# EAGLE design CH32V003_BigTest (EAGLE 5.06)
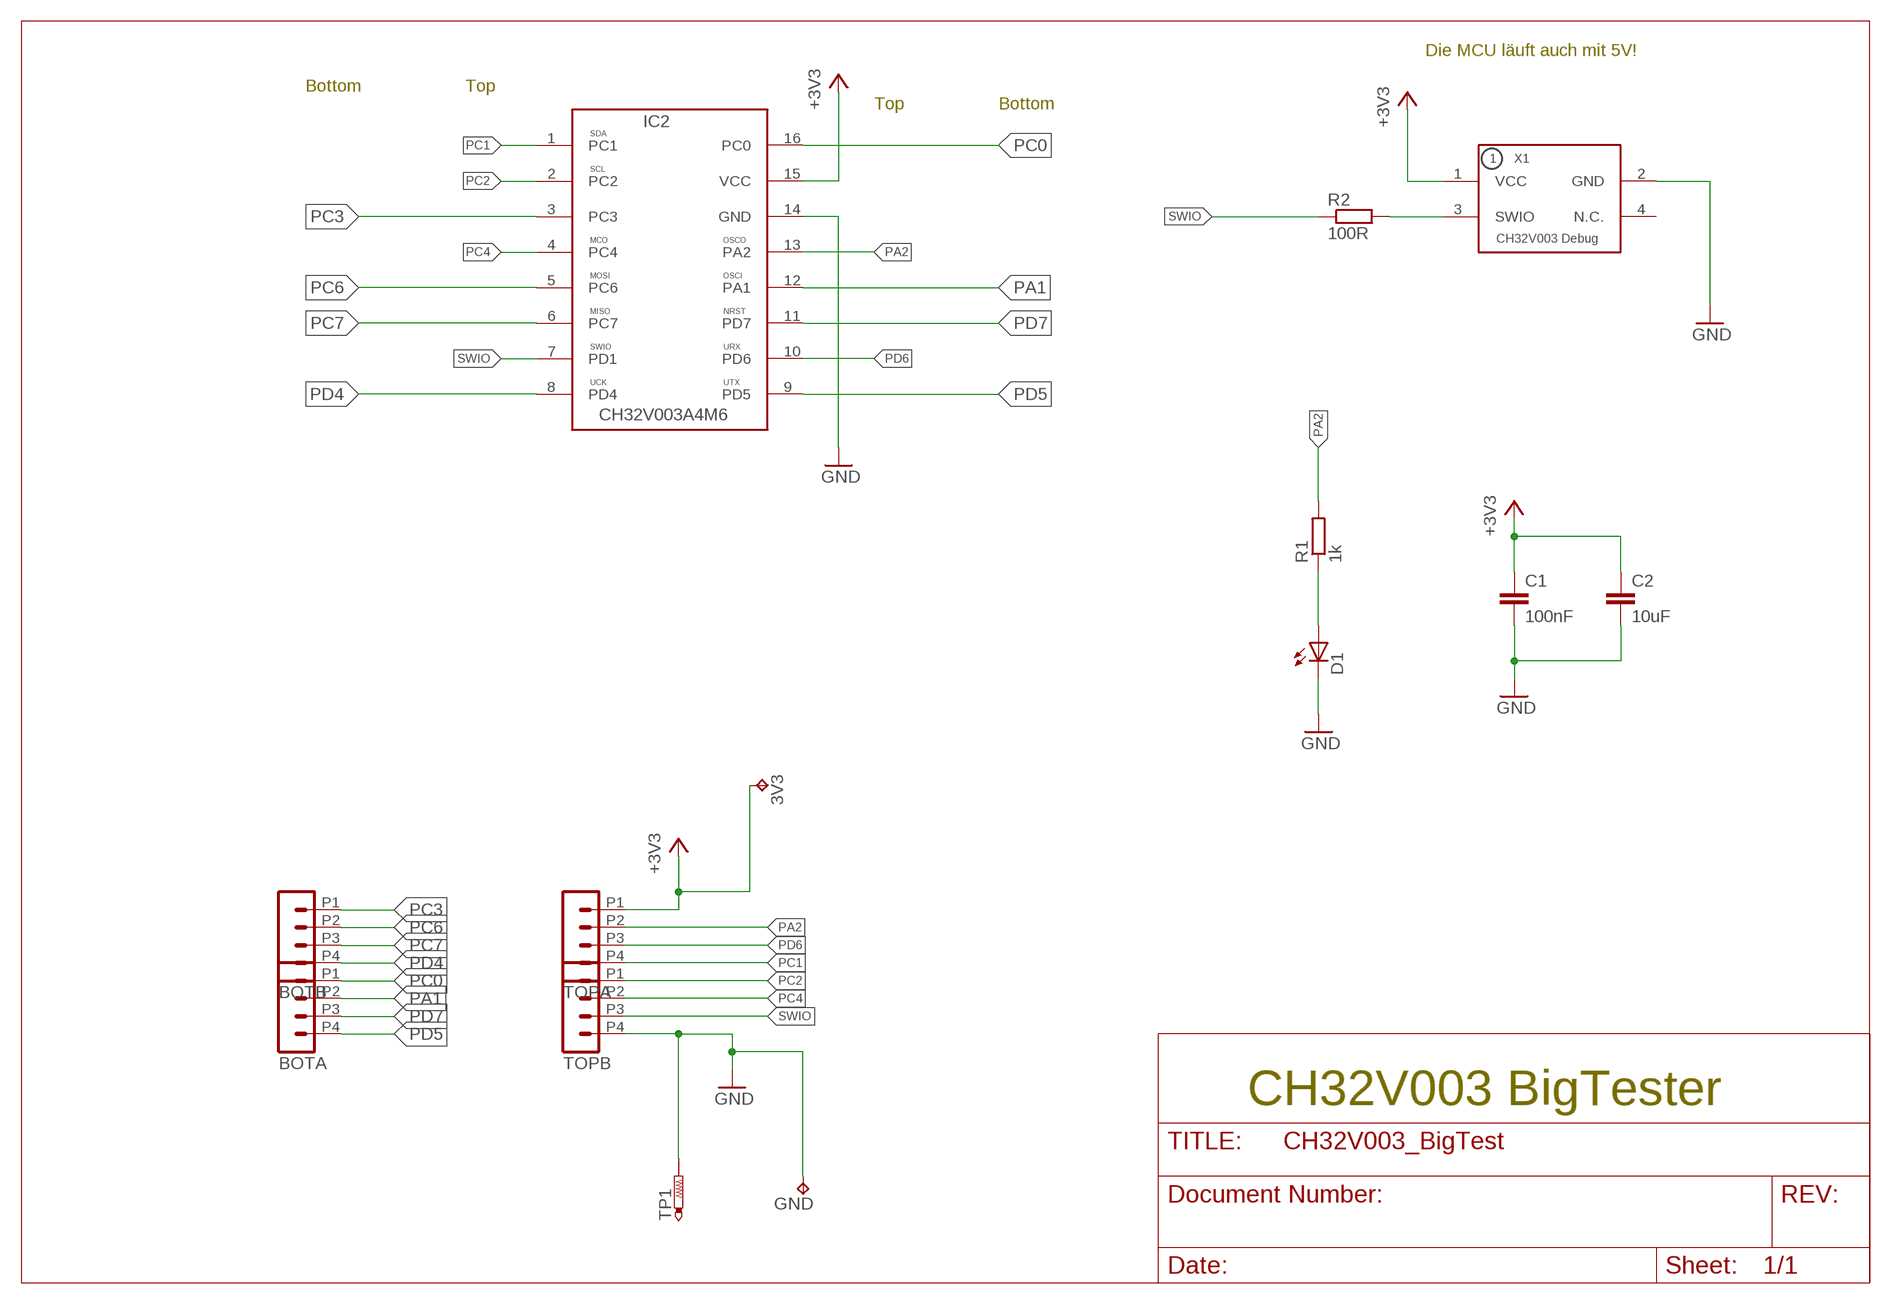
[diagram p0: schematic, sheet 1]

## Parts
3V3  TPB2,54  [B2,54]
BOTA  MA04-1SMD  [MA04-1SMD]
BOTB  MA04-1SMD  [MA04-1SMD]
C1  100nF  C-EUC0603  [C0603]
C2  10uF  C-EUC1210  [C1210]
D1  LEDCHIP-LED0603  [CHIP-LED0603]
GND  TPB2,54  [B2,54]
IC2  CH32V003A4M6  [SO16]
R1  1k  R-EU_R0603  [R0603]
R2  100R  R-EU_R0603  [R0603]
TOPA  MA04-1SMD  [MA04-1SMD]
TOPB  MA04-1SMD  [MA04-1SMD]
TP1  GND  TEST_OESE  [TEST_HAKEN]
X1  CH32V003_DEBUG  [CH32V003_DEBUG]

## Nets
+3V3: 3V3.PP(TP) C1.1 C2.1 IC2.15(VCC) TOPA.P1 X1.1(VCC)
GND: C1.2 C2.2 D1.C GND.PP(TP) IC2.14(GND) TOPB.P4 TP1.P$1(TP) X1.2(GND)
N$1: R2.2 X1.3(SWIO)
N$2: D1.A R1.1
PA1: BOTA.P2 IC2.12(PA1)
PA2: IC2.13(PA2) R1.2 TOPA.P2
PC0: BOTA.P1 IC2.16(PC0)
PC1: IC2.1(PC1) TOPA.P4
PC2: IC2.2(PC2) TOPB.P1
PC3: BOTB.P1 IC2.3(PC3)
PC4: IC2.4(PC4) TOPB.P2
PC6: BOTB.P2 IC2.5(PC6)
PC7: BOTB.P3 IC2.6(PC7)
PD4: BOTB.P4 IC2.8(PD4)
PD5: BOTA.P4 IC2.9(PD5)
PD6: IC2.10(PD6) TOPA.P3
PD7: BOTA.P3 IC2.11(PD7)
SWIO: IC2.7(PD1) R2.1 TOPB.P3
Unconnected: X1.4(N.C.)

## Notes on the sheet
- Die MCU läuft auch mit 5V!
- Bottom | Top
- Top | Bottom
- CH32V003 BigTester

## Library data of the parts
3V3 GND = testpad:TP: Test pad
BOTA BOTB TOPA TOPB = con-lstb:MA04-1SMD
C1 C2 = rcl:C-EU: CAPACITOR, European symbol
D1 = led:LED: LED
IC2 = olaf_V5:CH32V003A4M6: CH32V003 in SOT16
R1 R2 = rcl:R-EU_: RESISTOR, European symbol
TP1 = olaf_V5:TEST_OESE: Testpunkt fuer den Einsatz einer der Oesen von denen wir 100000Stk haben
X1 = olaf_V5:CH32V003_DEBUG: CH32V003 Debugstecker

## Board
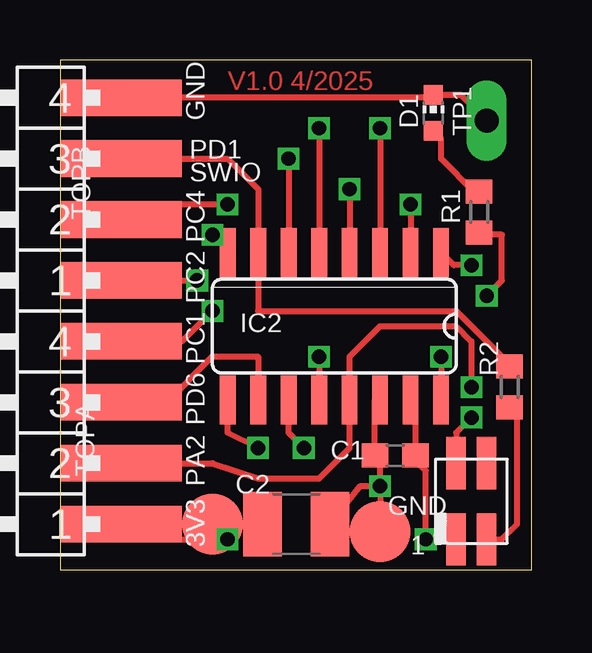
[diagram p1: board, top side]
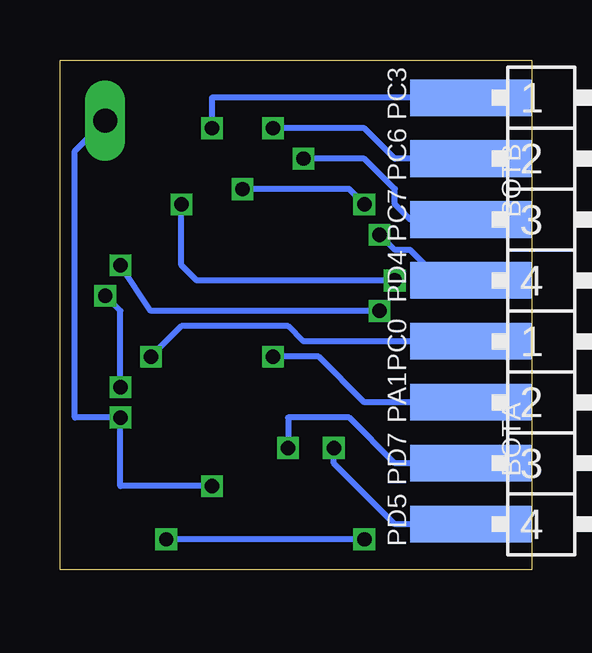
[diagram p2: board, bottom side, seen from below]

Size 19.66 x 21.26 mm. Coordinates in mm from the lower left corner, seen from the top.
Outline: 0,0 19.66,0 19.66,21.26 0,21.26 0,0
Copper layers (1*16): Top 0.035mm / dielectric 1.6mm / Bottom 0.035mm
Design rules "Elecrow_2-layer_PCB_eagle_rule": minimum track width 6mil, minimum drill 12mil, track to track 6mil, track to pad 6mil, pad to pad 6mil, via to via 8mil, smd to smd 0mil, copper to edge 20mil, drill to drill 10mil, minimum pad ring 6mil, minimum via ring 6mil, stop-mask expansion 0mil, vias tented up to drill 100mil, thermal gap 10mil

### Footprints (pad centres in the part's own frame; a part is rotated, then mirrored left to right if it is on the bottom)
B2,54 = smd 2.54 x 2.54: PP 0,0
MA04-1SMD = smd 1.524 x 5.08: P1 -3.81,-3.81; P2 -1.27,-3.81; P3 1.27,-3.81; P4 3.81,-3.81
C0603 = smd 1.1 x 1: 1 -0.85,0; 2 0.85,0
C1210 = smd 1.6 x 2.7: 1 -1.4,0; 2 1.4,0
CHIP-LED0603 = smd 0.8 x 0.8: A 0,-0.75; C 0,0.75
SO16 = smd 0.66 x 2.032: 1 -4.445,-3.073; 2 -3.175,-3.073; 3 -1.905,-3.073; 4 -0.635,-3.073; 5 0.635,-3.073; 6 1.905,-3.073; 7 3.175,-3.073; 8 4.445,-3.073; 9 4.445,3.073; 10 3.175,3.073; 11 1.905,3.073; 12 0.635,3.073; 13 -0.635,3.073; 14 -1.905,3.073; 15 -3.175,3.073; 16 -4.445,3.073
R0603 = smd 1 x 1.1: 1 -0.85,0; 2 0.85,0
TEST_HAKEN = drill 1 pad 1.676 long: P$1 0,0
CH32V003_DEBUG = smd 0.813 x 2.184: 1 -0.635,-1.587; 2 -0.635,1.587; 3 0.635,-1.587; 4 0.635,1.587

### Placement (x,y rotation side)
3V3  6.35,1.91 0 top
BOTA  -1.27,5.71 270 bottom
BOTB  -1.27,15.88 270 bottom
C1  13.97,4.76 180 top
C2  9.84,1.91 0 top
D1  15.56,19.05 0 top
GND  13.34,1.59 0 top
IC2  11.43,10.16 180 top
R1  17.46,14.92 270 top
R2  18.73,7.62 270 top
TOPA  -1.27,5.71 90 top
TOPB  -1.27,15.88 90 top
TP1  17.78,18.73 90 top
X1  17.14,2.86 0 top

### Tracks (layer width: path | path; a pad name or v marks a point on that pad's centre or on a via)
+3V3  (via drill 0.6)
  Top 0.254: IC2.15 14.82,7.09 C1.1 | C1.1 14.61,4.55 | v6.99,1.27 7.62,1.91 C2.1 | TOPA.P1 3.17,1.27 v6.99,1.27 | X1.1 v15.24,1.27 15.24,4.13 14.82,4.55 C1.1 | v6.99,1.27 3V3.PP
  Bottom 0.254: v6.99,1.27 v15.24,1.27
GND  (via drill 0.6)
  Top 0.254: IC2.14 13.12,7.09 C1.2 13.34,4.55 v13.34,3.49 | TOPB.P4 15.44,19.68 D1.C 16.71,19.8 TP1.P$1 | v17.14,6.35 16.51,5.71 X1.2 | C2.2 12.51,3.49 v13.34,3.49 | v13.34,3.49 GND.PP
  Bottom 0.254: TP1.P$1 19.05,17.46 19.05,6.35 v17.14,6.35 17.14,3.49 v13.34,3.49
N$1
  Top 0.254: X1.3 18.41,1.27 19.05,1.91 19.05,6.45 R2.2
N$2
  Top 0.254: R1.1 17.25,15.77 15.88,17.14 15.88,17.98 D1.A
PA1  (via drill 0.6)
  Top 0.254: v10.79,8.89 IC2.12
  Bottom 0.254: BOTA.P2 6.99,6.99 8.89,8.89 v10.79,8.89
PA2  (via drill 0.6)
  Top 0.254: TOPA.P2 6.35,4.45 8.26,3.81 10.79,3.81 12.06,5.08 IC2.13 12.06,8.89 13.34,10.16 16.51,10.16 17.14,9.53 v17.14,7.62 | R1.2 17.57,13.97 18.41,13.97 18.41,12.06 v17.78,11.43
  Bottom 0.254: v17.78,11.43 17.14,10.79 v17.14,7.62
PC0  (via drill 0.6)
  Top 0.254: v15.88,8.89 IC2.16
  Bottom 0.254: BOTA.P1 9.53,9.53 10.16,10.16 14.61,10.16 v15.88,8.89
PC1  (via drill 0.6)
  Top 0.254: TOPA.P4 5.08,9.53 v6.35,10.79 | v17.14,12.7 16.41,12.7 IC2.1
  Bottom 0.254: v6.35,10.79 15.88,10.79 v17.14,12.7
PC2  (via drill 0.6)
  Top 0.254: TOPB.P1 v5.71,12.06 | v14.61,15.24 IC2.2
  Bottom 0.254: v5.71,12.06 13.97,12.06 14.61,12.7 v14.61,15.24
PC3  (via drill 0.6)
  Top 0.254: v13.34,18.41 IC2.3
  Bottom 0.254: v13.34,18.41 13.34,19.68 BOTB.P1
PC4  (via drill 0.6)
  Top 0.254: v12.06,15.88 IC2.4 | v6.99,15.24 3.17,15.24 TOPB.P2
  Bottom 0.254: v12.06,15.88 7.62,15.88 v6.99,15.24
PC6  (via drill 0.6)
  Top 0.254: v10.79,18.41 IC2.5
  Bottom 0.254: v10.79,18.41 6.99,18.41 5.71,17.14 BOTB.P2
PC7  (via drill 0.6)
  Top 0.254: v9.53,17.14 IC2.6
  Bottom 0.254: BOTB.P3 5.08,14.61 5.71,15.24 5.71,15.88 6.99,17.14 v9.53,17.14
PD4  (via drill 0.6)
  Top 0.254: IC2.8 6.99,13.34 v6.35,13.97
  Bottom 0.254: BOTB.P4 3.81,12.06 5.08,13.34 5.71,13.34 v6.35,13.97
PD5  (via drill 0.6)
  Top 0.254: IC2.9 6.99,5.71 v8.26,5.08
  Bottom 0.254: v8.26,5.08 8.26,4.45 5.71,1.91 BOTA.P4
PD6
  Top 0.254: TOPA.P3 4.45,6.99 6.35,8.89 8.26,8.89 IC2.10
PD7  (via drill 0.6)
  Top 0.254: IC2.11 9.53,5.71 v10.16,5.08
  Bottom 0.254: v10.16,5.08 10.16,6.35 7.62,6.35 5.71,4.45 BOTA.P3
SWIO
  Top 0.254: R2.1 18.73,8.57 16.51,10.79 8.26,10.79 IC2.7 8.26,15.88 6.99,17.14 TOPB.P3

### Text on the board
Top: V1.0 4/2025
tNames: GND | PD1 | SWIO | PC4 | PC2 | PC1 | PD6 | PA2 | 3V3 | 1
bNames: PC3 | PC6 | PC7 | PD4 | PC0 | PA1 | PD7 | PD5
